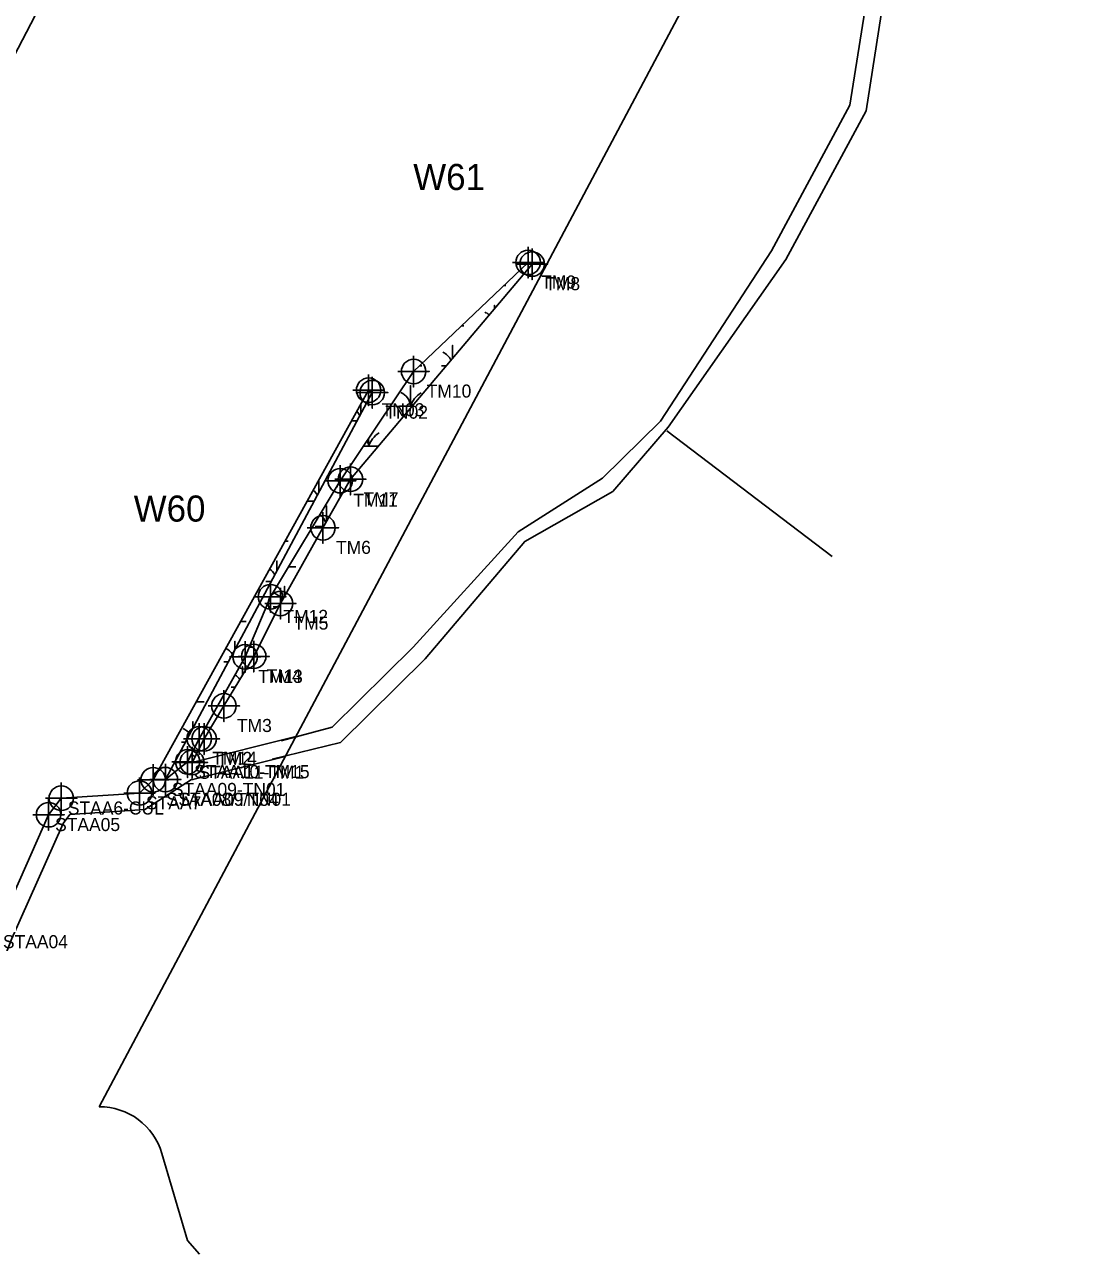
# Model space of a CAD drawing. Extents: x 1253697 to 1278588, y 912189 to 981699.
# Drawn here: x 1254577 to 1255398, y 954967 to 955905 of the extents above; entities that cross this region are included whole.
import ezdxf

# ---------------------------------------------------------------- set-up
doc = ezdxf.new("R2010")
doc.units = 0
for name, color, linetype in [('Default', 7, 'Continuous'), ('Exist Environmental Wetland Boundary', 7, 'Continuous'), ('Exist Environmental Wetland Boundary Cogo Comment', 7, 'Continuous'), ('Exist Environmental Wetland Boundary Cogo Number', 7, 'Continuous'), ('Exist Environmental Wetland Boundary Cogo Point CELL', 7, 'Continuous'), ('Exist Hydro Jurisdictional Stream or Body of Water Mitigable', 7, 'Continuous'), ('Exist Hydro Jurisdictional Stream or Body of Water Mitigable Cogo Comment', 7, 'Continuous'), ('Exist Hydro Jurisdictional Stream or Body of Water Mitigable Cogo Point CELL', 7, 'Continuous'), ('Exist Hydro Swamp or Marsh', 7, 'Continuous')]:
    doc.layers.add(name, color=color, linetype=linetype)

msp = doc.modelspace()

# ---------------------------------------------------------------- linework, layer by layer
at = {"layer": 'Default'}
msp.add_line((1254634.04, 955075.64), (1255397.66, 956512.98), dxfattribs=at)
msp.add_line((1254634.04, 955075.64), (1255397.66, 956512.98), dxfattribs=at)
for points in [[(1254696.64, 956137.98), (1254679.34, 956093.11), (1254545.8, 955836.6), (1254507.05, 955857.72)], [(1254696.64, 956137.98), (1254679.34, 956093.11), (1254545.8, 955836.6), (1254507.05, 955857.72)], [(1254711.14, 954962.56), (1254701.96, 954973.12), (1254682.25, 955039.81)], [(1254711.14, 954962.56), (1254701.96, 954973.12), (1254682.25, 955039.81)]]:
    msp.add_lwpolyline(points, dxfattribs=at)
msp.add_arc((1254634.3, 955025.64), 50, 16.46913, 90.29173, dxfattribs=at)
msp.add_arc((1254634.3, 955025.64), 50, 16.46913, 90.29173, dxfattribs=at)
at = {"layer": 'Exist Environmental Wetland Boundary'}
for points in [[(1254701.96, 955339.89), (1254710.81, 955357.62), (1254745.98, 955420.36), (1254765.34, 955466.35), (1254818.86, 955555.33), (1254875.13, 955639.02), (1254962.86, 955722.6), (1254965.92, 955721.33), (1254826.73, 955556.48), (1254805.64, 955519.23), (1254773.08, 955461.23), (1254752.58, 955420.74), (1254729.72, 955382.76), (1254714.58, 955357.5), (1254705.29, 955339.4)], [(1254684.89, 955326.24), (1254675.55, 955326.13), (1254840.65, 955624.7), (1254843.41, 955622.84), (1254684.89, 955326.24)]]:
    msp.add_lwpolyline(points, dxfattribs=at)
at = {"layer": 'Exist Environmental Wetland Boundary Cogo Point CELL'}
for points in [[(1254962.86, 955734.6), (1254962.86, 955710.6), (1254962.86, 955722.6), (1254974.86, 955722.6), (1254950.86, 955722.6)], [(1254965.92, 955733.33), (1254965.92, 955709.33), (1254965.92, 955721.33), (1254977.92, 955721.33), (1254953.92, 955721.33)], [(1254875.13, 955651.02), (1254875.13, 955627.02), (1254875.13, 955639.02), (1254887.13, 955639.02), (1254863.13, 955639.02)], [(1254840.65, 955636.7), (1254840.65, 955612.7), (1254840.65, 955624.7), (1254852.65, 955624.7), (1254828.65, 955624.7)], [(1254843.41, 955634.84), (1254843.41, 955610.84), (1254843.41, 955622.84), (1254855.41, 955622.84), (1254831.41, 955622.84)], [(1254818.86, 955567.33), (1254818.86, 955543.33), (1254818.86, 955555.33), (1254830.86, 955555.33), (1254806.86, 955555.33)], [(1254826.73, 955568.48), (1254826.73, 955544.48), (1254826.73, 955556.48), (1254838.73, 955556.48), (1254814.73, 955556.48)], [(1254805.64, 955531.23), (1254805.64, 955507.23), (1254805.64, 955519.23), (1254817.64, 955519.23), (1254793.64, 955519.23)], [(1254765.34, 955478.35), (1254765.34, 955454.35), (1254765.34, 955466.35), (1254777.34, 955466.35), (1254753.34, 955466.35)], [(1254773.08, 955473.23), (1254773.08, 955449.23), (1254773.08, 955461.23), (1254785.08, 955461.23), (1254761.08, 955461.23)], [(1254745.98, 955432.36), (1254745.98, 955408.36), (1254745.98, 955420.36), (1254757.98, 955420.36), (1254733.98, 955420.36)], [(1254752.58, 955432.74), (1254752.58, 955408.74), (1254752.58, 955420.74), (1254764.58, 955420.74), (1254740.58, 955420.74)], [(1254729.72, 955394.76), (1254729.72, 955370.76), (1254729.72, 955382.76), (1254741.72, 955382.76), (1254717.72, 955382.76)], [(1254710.81, 955369.63), (1254710.81, 955345.63), (1254710.81, 955357.62), (1254722.81, 955357.62), (1254698.81, 955357.62)], [(1254714.58, 955369.5), (1254714.58, 955345.5), (1254714.58, 955357.5), (1254726.58, 955357.5), (1254702.58, 955357.5)], [(1254675.55, 955338.13), (1254675.55, 955314.13), (1254675.55, 955326.13), (1254687.55, 955326.13), (1254663.55, 955326.13)], [(1254684.89, 955338.25), (1254684.89, 955314.25), (1254684.89, 955326.24), (1254696.89, 955326.24), (1254672.89, 955326.24)]]:
    msp.add_lwpolyline(points, dxfattribs=at)
for centre in [(1254962.86, 955722.6), (1254965.92, 955721.33), (1254875.13, 955639.02), (1254840.65, 955624.7), (1254843.41, 955622.84), (1254818.86, 955555.33), (1254826.73, 955556.48), (1254805.64, 955519.23), (1254765.34, 955466.35), (1254773.08, 955461.23), (1254745.98, 955420.36), (1254752.58, 955420.74), (1254729.72, 955382.76), (1254710.81, 955357.62), (1254714.58, 955357.5), (1254675.55, 955326.13), (1254684.89, 955326.24)]:
    msp.add_circle(centre, 9.38, dxfattribs=at)
at = {"layer": 'Exist Hydro Jurisdictional Stream or Body of Water Mitigable'}
msp.add_line((1255069.25, 955593.49), (1255195.79, 955497.17), dxfattribs=at)
for points in [[(1254773.69, 955356.01), (1254812.59, 955366.36), (1254874.76, 955427.85), (1254955.26, 955516.27), (1255019.84, 955557.25), (1255064.25, 955600.99), (1255149.28, 955731.42), (1255209.46, 955842.98), (1255222.57, 955926.93), (1255346.15, 956050.17), (1255419.08, 956093.7), (1255471.85, 956221.78), (1255479.46, 956338.17), (1255514.41, 956421.93), (1255531.58, 956428.79), (1255553.58, 956479.5), (1255609.22, 956590.97), (1255636.38, 956630.95), (1255675.38, 956719.43), (1255701.33, 956798.33), (1255734.85, 956846.46), (1255731.48, 956895.97), (1255696.9, 956998.09), (1255633.04, 957047.13)], [(1255707.82, 957005.9), (1255707.82, 957005.9), (1255742.07, 956906.95), (1255747.98, 956842.82), (1255712.95, 956792.53), (1255687.39, 956714.82), (1255647.67, 956624.69), (1255620.34, 956584.46), (1255565.23, 956474.07), (1255541.27, 956418.82), (1255524.2, 956412), (1255492.14, 956335.2), (1255484.54, 956218.83), (1255429.34, 956084.85), (1255354.1, 956039.95), (1255234.62, 955920.79), (1255221.82, 955838.82), (1255160.34, 955724.85), (1255070.23, 955596.42), (1255027.89, 955547.13), (1254960.26, 955508.77), (1254884.04, 955418.95), (1254819.13, 955354.75), (1254766.64, 955341.9)], [(1254558.2, 953978.81), (1254478.51, 954119.21), (1254445.35, 954200.44), (1254401.39, 954397.58), (1254390.69, 954546.32), (1254394.28, 954639.24), (1254399.81, 954647.94), (1254423.24, 954837.79), (1254430.69, 954897.75), (1254438.43, 954931.33), (1254463.4, 955005.06), (1254467.81, 955035.86), (1254514.59, 955104.88), (1254555.42, 955209.58), (1254595.38, 955299.35), (1254605.12, 955312.03), (1254665.04, 955316.01), (1254675.55, 955326.13), (1254684.89, 955326.24), (1254701.96, 955339.89), (1254705.29, 955339.4), (1254784.78, 955359.37)], [(1254776.66, 955344.08), (1254705.95, 955326.31), (1254704.87, 955326.46), (1254669.22, 955303.4), (1254611.78, 955299.59), (1254606.51, 955292.73), (1254567.29, 955204.62), (1254526.04, 955098.86), (1254480.12, 955031.1), (1254476.13, 955003.24), (1254458.85, 954928.27), (1254451.11, 954894.68), (1254443.67, 954834.73), (1254420.23, 954644.88), (1254414.71, 954636.18), (1254411.12, 954543.25), (1254421.82, 954394.51), (1254465.78, 954197.38), (1254498.94, 954116.15), (1254578.62, 953975.74)]]:
    msp.add_lwpolyline(points, dxfattribs=at)
at = {"layer": 'Exist Hydro Jurisdictional Stream or Body of Water Mitigable Cogo Point CELL'}
for points in [[(1254701.96, 955351.89), (1254701.96, 955327.89), (1254701.96, 955339.89), (1254713.96, 955339.89), (1254689.96, 955339.89)], [(1254705.29, 955351.4), (1254705.29, 955327.4), (1254705.29, 955339.4), (1254717.29, 955339.4), (1254693.29, 955339.4)], [(1254605.12, 955324.03), (1254605.12, 955300.03), (1254605.12, 955312.03), (1254617.12, 955312.03), (1254593.12, 955312.03)], [(1254665.04, 955328.01), (1254665.04, 955304.01), (1254665.04, 955316.01), (1254677.04, 955316.01), (1254653.04, 955316.01)], [(1254595.38, 955311.35), (1254595.38, 955287.35), (1254595.38, 955299.35), (1254607.38, 955299.35), (1254583.38, 955299.35)]]:
    msp.add_lwpolyline(points, dxfattribs=at)
for centre in [(1254701.96, 955339.89), (1254705.29, 955339.4), (1254665.04, 955316.01), (1254605.12, 955312.03), (1254595.38, 955299.35)]:
    msp.add_circle(centre, 9.38, dxfattribs=at)
at = {"layer": 'Exist Hydro Swamp or Marsh'}
for p, q in [((1254944.19, 955704.81), (1254945.8, 955704.81)), ((1254911.87, 955674.03), (1254913.59, 955674.03)), ((1254879.56, 955643.25), (1254881.39, 955643.25)), ((1254896.39, 955643.25), (1254899.99, 955643.25)), ((1254834.77, 955606.68), (1254834.77, 955614.07)), ((1254834.77, 955614.07), (1254834.77, 955606.68)), ((1254827.67, 955601.23), (1254831.86, 955601.23)), ((1254810.65, 955570.45), (1254811.17, 955570.45)), ((1254816.2, 955550.9), (1254816.98, 955550.9)), ((1254793.97, 955539.67), (1254798.96, 955539.67)), ((1254799.78, 955520.12), (1254806.15, 955520.12)), ((1254776.61, 955508.89), (1254778.97, 955508.89)), ((1254779.17, 955489.34), (1254784.78, 955489.34)), ((1254761.76, 955478.11), (1254766.06, 955478.11)), ((1254767.58, 955458.56), (1254771.73, 955458.56)), ((1254742.57, 955447.33), (1254746.76, 955447.33)), ((1254749.1, 955427.78), (1254752.58, 955427.78)), ((1254729.56, 955416.55), (1254733.15, 955416.55)), ((1254735.37, 955397), (1254738.29, 955397)), ((1254708.53, 955385.77), (1254714.56, 955385.77)), ((1254715.63, 955366.22), (1254719.81, 955366.22)), ((1254697.36, 955354.99), (1254700.25, 955354.99))]:
    msp.add_line(p, q, dxfattribs=at)
for points in [[(1254937.19, 955687.31), (1254937.19, 955689.81), (1254937.19, 955687.31)], [(1254904.99, 955649.16), (1254904.99, 955659.03), (1254904.99, 955649.16)], [(1254864.19, 955612.47), (1254872.79, 955612.47), (1254872.79, 955628.25), (1254872.79, 955612.47), (1254874.01, 955612.47)], [(1254836.58, 955581.69), (1254840.58, 955581.69), (1254840.58, 955587.64)], [(1254840.58, 955587.64), (1254840.58, 955581.69), (1254848.02, 955581.69)], [(1254802.57, 955546.43), (1254802.57, 955555.45), (1254802.57, 955546.43)], [(1254808.38, 955524.07), (1254808.38, 955535.9), (1254808.38, 955524.07)], [(1254770.37, 955486.17), (1254770.37, 955493.89), (1254770.37, 955486.17)], [(1254776.18, 955466.74), (1254776.18, 955474.34), (1254776.18, 955466.74)], [(1254738.16, 955425.92), (1254738.16, 955432.33), (1254738.16, 955425.92)], [(1254743.97, 955406.45), (1254743.97, 955412.78), (1254743.97, 955406.45)], [(1254705.96, 955365.67), (1254705.96, 955370.77), (1254705.96, 955365.67)]]:
    msp.add_lwpolyline(points, dxfattribs=at)
for centre, radius, start, end in [((1254924.93, 955673.14), 12.3, 48.73786, 67.53497), ((1254892.72, 955642.36), 12.3, 25.92986, 67.53497), ((1254860.52, 955611.58), 12.3, 4.14034, 67.53497), ((1254891.03, 955606.41), 19.22, 122.12745, 161.62219), ((1254822.51, 955600.35), 12.3, 22.31979, 41.62122), ((1254828.32, 955580.8), 12.3, 4.14034, 24.94326), ((1254858.83, 955575.62), 19.22, 122.12745, 161.62219), ((1254790.3, 955538.78), 12.3, 25.95311, 49.40101), ((1254796.11, 955519.24), 12.3, 18.07123, 54.83791), ((1254758.1, 955477.22), 12.3, 29.42643, 56.96715), ((1254763.91, 955457.68), 12.3, 30.09939, 67.53497), ((1254725.9, 955415.66), 12.3, 32.77056, 64.46195), ((1254731.71, 955396.11), 12.3, 34.04766, 57.98572), ((1254693.69, 955354.1), 12.3, 36.00926, 67.53497), ((1254699.5, 955334.55), 12.3, 49.00756, 64.3575), ((1254692, 955318.15), 19.22, 122.12745, 132.77503)]:
    msp.add_arc(centre, radius, start, end, dxfattribs=at)

# ---------------------------------------------------------------- texts
at = {"layer": 'Exist Environmental Wetland Boundary Cogo Comment'}
for s, p in [('TM9', (1254972.86, 955702.6)), ('TM8', (1254975.92, 955701.33)), ('TM10', (1254885.13, 955619.02)), ('TN03', (1254850.65, 955604.7)), ('TN02', (1254853.41, 955602.84)), ('TM11', (1254828.86, 955535.33)), ('TM7', (1254836.73, 955536.48)), ('TM6', (1254815.64, 955499.23)), ('TM12', (1254775.34, 955446.35)), ('TM5', (1254783.08, 955441.23)), ('TM13', (1254755.98, 955400.36)), ('TM4', (1254762.58, 955400.74)), ('TM3', (1254739.72, 955362.76)), ('TM14', (1254720.81, 955337.62)), ('TM2', (1254724.58, 955337.5)), ('STAA08/TN04', (1254685.55, 955306.13)), ('STAA09/TN01', (1254694.89, 955306.24))]:
    msp.add_text(s, height=10, dxfattribs=at).set_placement(p)
at = {"layer": 'Exist Environmental Wetland Boundary Cogo Number'}
for s, p in [('W61', (1254874.81, 955778.07)), ('W60', (1254660.61, 955523.98))]:
    msp.add_text(s, height=20, dxfattribs=at).set_placement(p)
at = {"layer": 'Exist Hydro Jurisdictional Stream or Body of Water Mitigable Cogo Comment'}
for s, p in [('STAA10-TM15', (1254706.96, 955327.39)), ('STAA11-TM1', (1254710.29, 955326.9)), ('STAA09-TN01', (1254689.89, 955313.74)), ('STAA7', (1254670.04, 955303.51)), ('STAA6-CUL', (1254610.12, 955299.53)), ('STAA05', (1254600.38, 955286.85)), ('STAA04', (1254560.42, 955197.08))]:
    msp.add_text(s, height=10, dxfattribs=at).set_placement(p)

doc.saveas('drawing.dxf')
